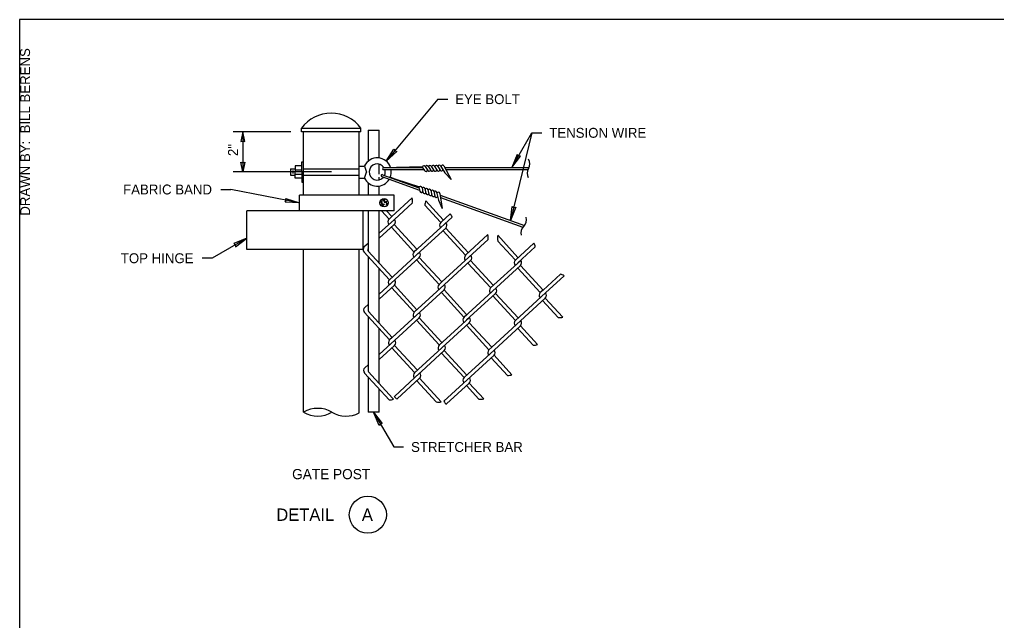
# Model space of a CAD drawing. Extents: x 99862 to 104211, y 98939 to 105076.
# Drawn here: x 99862 to 101442, y 104103 to 105076 of the extents above; entities that cross this region are included whole.
import ezdxf

# ---------------------------------------------------------------- set-up
doc = ezdxf.new("R2010")
doc.units = 0
for name, color, linetype in [('Level 1', 7, 'Continuous'), ('Level 15', 7, 'Continuous'), ('Level 2', 7, 'Continuous'), ('Level 20', 7, 'Continuous'), ('Level 4', 7, 'Continuous'), ('Level 62', 7, 'Continuous'), ('Level 7', 7, 'Continuous'), ('Level 9', 7, 'Continuous')]:
    doc.layers.add(name, color=color, linetype=linetype)

msp = doc.modelspace()

# ---------------------------------------------------------------- linework, layer by layer
at = {"layer": 'Level 1'}
msp.add_lwpolyline([(99862, 102999.5), (103151, 102999.5), (103151, 105075.5), (99862, 105075.5)], close=True, dxfattribs=at)
at = {"layer": 'Level 15'}
for p, q in [((100538.7, 104946.7), (100455.2, 104846.3)), ((100538.7, 104946.7), (100554.7, 104946.7)), ((100230.6, 104893.6), (100207.3, 104893.6)), ((100223.3, 104893.6), (100223.3, 104828.9)), ((100300.6, 104893.6), (100230.6, 104893.6)), ((100690.8, 104892.2), (100656.4, 104750.2)), ((100658.3, 104835.9), (100690.8, 104892.2)), ((100690.8, 104892.2), (100706.8, 104892.2)), ((100366.4, 104828.9), (100207.3, 104828.9)), ((100187.6, 104800.5), (100203.6, 104800.5)), ((100314.8, 104778.7), (100203.6, 104800.5)), ((100229.7, 104721.8), (100173.4, 104689.3)), ((100173.4, 104689.3), (100157.4, 104689.3)), ((100434.8, 104440.1), (100467.3, 104383.9)), ((100467.3, 104383.9), (100483.3, 104383.9))]:
    msp.add_line(p, q, dxfattribs=at)
for points in [[(100223.3, 104893.6), (100220.2, 104877.9), (100223.3, 104878.6), (100226.3, 104877.9)], [(100223.3, 104893.6), (100220.2, 104877.9), (100223.3, 104878.6), (100226.3, 104877.9)], [(100455.2, 104846.3), (100467.5, 104865.7), (100469.1, 104863), (100472.1, 104861.9)], [(100658.3, 104835.9), (100672.3, 104854.2), (100669.1, 104854.7), (100667.1, 104857.1)], [(100223.3, 104828.9), (100220.2, 104844.6), (100223.3, 104843.9), (100226.3, 104844.6)], [(100314.8, 104778.7), (100291.8, 104780.1), (100293.4, 104782.9), (100293, 104786)], [(100656.4, 104750.2), (100658.9, 104773.1), (100661.5, 104771.4), (100664.7, 104771.7)], [(100229.7, 104721.8), (100208.4, 104713), (100210.8, 104710.9), (100211.4, 104707.8)], [(100434.8, 104440.1), (100448.8, 104421.9), (100445.7, 104421.3), (100443.7, 104418.9)]]:
    msp.add_lwpolyline(points, close=True, dxfattribs=at)
at = {"layer": 'Level 2'}
for p, q in [((100300.2, 104834), (100300.2, 104823.6)), ((100300.2, 104834), (100307.8, 104834)), ((100304.2, 104831.4), (100304.2, 104826.2)), ((100307.8, 104838.9), (100307.8, 104828.8)), ((100307.9, 104832.2), (100318.4, 104832.2)), ((100321.2, 104834), (100411.5, 104834)), ((100420, 104838.5), (100423, 104828.8)), ((100450.9, 104836), (100513.4, 104835.9)), ((100450.9, 104832.7), (100515.8, 104832.7)), ((100462.1, 104836.3), (100471.9, 104836.6)), ((100471.9, 104836.6), (100514, 104837.8)), ((100514.2, 104834.8), (100517, 104831.1)), ((100518.1, 104837.9), (100522.3, 104831.1)), ((100523.1, 104838.1), (100527.4, 104831.2)), ((100528, 104838.4), (100532.4, 104831.4)), ((100532.9, 104838.6), (100537.6, 104831.3)), ((100538, 104838.7), (100542.4, 104831.7)), ((100543, 104838.8), (100550.1, 104827.5)), ((100548.4, 104838.6), (100560.3, 104816.7)), ((100549.8, 104836.1), (100686.1, 104836.1)), ((100551.7, 104832.6), (100684.4, 104832.6)), ((100300.2, 104823.6), (100307.8, 104823.6)), ((100307.8, 104818.7), (100307.8, 104828.8)), ((100307.8, 104825.3), (100318.4, 104825.3)), ((100321.1, 104823.6), (100411.6, 104823.6)), ((100420, 104819), (100423, 104828.8)), ((100448, 104821.4), (100509, 104799.5)), ((100449.1, 104824.5), (100507.8, 104803.3)), ((100461.8, 104820.3), (100469, 104818)), ((100469, 104818), (100509.1, 104804.9)), ((100550.1, 104827.5), (100560.3, 104816.7)), ((100508.2, 104802), (100509.6, 104797.6)), ((100513, 104803.6), (100514.6, 104795.8)), ((100517.7, 104802.2), (100519.4, 104794.1)), ((100522.4, 104800.7), (100524.2, 104792.7)), ((100527.1, 104799.2), (100529.1, 104790.8)), ((100531.9, 104797.6), (100533.7, 104789.6)), ((100536.7, 104796), (100539.5, 104783)), ((100541.7, 104794), (100545.5, 104769.5)), ((100542.2, 104791.2), (100678.7, 104742.2)), ((100542.8, 104787.3), (100676.2, 104739.4)), ((100539.5, 104783), (100545.5, 104769.5))]:
    msp.add_line(p, q, dxfattribs=at)
for points in [[(100318.4, 104828.8), (100318.4, 104838.9), (100307.8, 104838.9)], [(100318.4, 104838.9), (100318.4, 104845.1), (100321.1, 104845.1)], [(100318.4, 104818.7), (100318.4, 104812.4), (100321.1, 104812.4), (100321.1, 104845.1)], [(100411.6, 104838.5), (100420, 104838.5)], [(100318.4, 104828.8), (100318.4, 104818.7), (100307.8, 104818.7)], [(100411.6, 104819), (100420, 104819)]]:
    msp.add_lwpolyline(points, dxfattribs=at)
msp.add_circle((100451.6, 104779), 6.76, dxfattribs=at)
for centre, radius, start, end in [((100440.6, 104828.8), 22.8, 18.3425, 154.6231), ((100672, 104842), 15.4, 330, 30), ((100440.6, 104828.8), 13, 33.4715, 320.4532), ((100450.9, 104834.3), 1.6, 92.6316, 272.6316), ((100440.6, 104828.8), 13, 334.9419, 17.7718), ((100440.6, 104828.8), 22.8, 337.2003, 10.0184), ((100516, 104836.5), 2.5, 29.8429, 222.7267), ((100519.2, 104832.3), 2.5, 208.4651, 356.4133), ((100521, 104836.7), 2.5, 28.1747, 168.7798), ((100524.4, 104832.4), 2.5, 211.7102, 348.8374), ((100526, 104836.8), 2.5, 26.119, 168.8374), ((100529.5, 104832.6), 2.5, 209.4537, 349.9106), ((100531, 104837), 2.5, 24.8575, 168.9693), ((100534.5, 104832.7), 2.5, 212.2145, 349.0096), ((100536, 104837.1), 2.5, 25.6492, 169.089), ((100539.5, 104832.9), 2.5, 204.8575, 348.3868), ((100541, 104837.3), 2.5, 27.3875, 169.0102), ((100544.5, 104833.1), 2.5, 212.3243, 346.9886), ((100546.2, 104837.4), 2.5, 28.445, 175.2837), ((100698.6, 104826.7), 15.4, 150, 206.9934), ((100440.6, 104828.8), 22.8, 205.3769, 329.0704), ((100448.4, 104823), 1.6, 72.8951, 252.8951), ((100510.5, 104803), 2.5, 10.1064, 202.9901), ((100515.3, 104801.5), 2.5, 8.4381, 149.0432), ((100520, 104799.9), 2.5, 6.3824, 149.1008), ((100524.8, 104798.4), 2.5, 5.1209, 149.2328), ((100529.5, 104796.8), 2.5, 5.9127, 149.3525), ((100512.1, 104798), 2.5, 188.7285, 336.6768), ((100517.1, 104796.3), 2.5, 191.9736, 329.1008), ((100521.8, 104794.8), 2.5, 189.7171, 330.174), ((100526.6, 104793.2), 2.5, 192.478, 329.273), ((100531.4, 104791.7), 2.5, 185.1209, 328.6502), ((100534.3, 104795.3), 2.5, 7.6509, 149.2736), ((100536.1, 104790.2), 2.5, 192.5877, 327.252), ((100539.3, 104793.7), 2.5, 8.7084, 155.5471), ((100666.6, 104751.7), 15.4, 314.8676, 14.8676), ((100688.3, 104729.9), 15.4, 134.8676, 191.861)]:
    msp.add_arc(centre, radius, start, end, dxfattribs=at)
at = {"layer": 'Level 4'}
for p, q in [((100497.1, 104786.9), (100464.2, 104756.6)), ((100497.7, 104779.2), (100468.3, 104752.2)), ((100517.5, 104775), (100542.9, 104747.4)), ((100519.2, 104782.1), (100547.3, 104751.4)), ((100468.3, 104752.2), (100443.9, 104729.8)), ((100447.4, 104766.1), (100459.8, 104752.6)), ((100455.5, 104766.1), (100464.2, 104756.6)), ((100464.2, 104756.6), (100459.8, 104752.6)), ((100561.6, 104755.8), (100500.4, 104699.5)), ((100558.7, 104761.3), (100543.2, 104747)), ((100467.9, 104743.8), (100443.9, 104721.7)), ((100459.5, 104744.1), (100459.5, 104744.1)), ((100463.5, 104739.7), (100500, 104699.9)), ((100467.9, 104743.8), (100504.4, 104704)), ((100551.3, 104738.2), (100504.4, 104695.1)), ((100542.9, 104747.4), (100543.2, 104747)), ((100542.9, 104738.5), (100542.9, 104738.5)), ((100547.3, 104751.4), (100547.6, 104751.1)), ((100551.3, 104738.2), (100587.9, 104698.4)), ((100546.9, 104734.1), (100583.4, 104694.3)), ((100619.6, 104727.5), (100583.4, 104694.3)), ((100635.4, 104726.4), (100668.2, 104690.7)), ((100425.7, 104713.2), (100419.7, 104707.6)), ((100620, 104719.8), (100545, 104650.9)), ((100635.9, 104717.1), (100663.8, 104686.7)), ((100694.1, 104713.8), (100664.1, 104686.3)), ((100696.3, 104707.7), (100668.2, 104681.9)), ((100419.3, 104699.1), (100459.9, 104654.9)), ((100425.8, 104701), (100464.3, 104659)), ((100508.5, 104690.7), (100443.9, 104631.4)), ((100508.8, 104699.2), (100460.2, 104654.5)), ((100500, 104699.9), (100500.4, 104699.5)), ((100500, 104691.1), (100500, 104691.1)), ((100504.8, 104703.6), (100500.4, 104699.5)), ((100504.4, 104704), (100504.8, 104703.6)), ((100508.5, 104690.7), (100545, 104650.9)), ((100668.5, 104690.3), (100664.1, 104686.3)), ((100668.2, 104690.7), (100668.5, 104690.3)), ((100504.1, 104686.6), (100540.6, 104646.9)), ((100591.5, 104685.5), (100549.1, 104646.5)), ((100672.2, 104677.4), (100581.1, 104593.8)), ((100583.1, 104685.9), (100583.1, 104685.9)), ((100587.1, 104681.4), (100623.6, 104641.7)), ((100591.5, 104685.5), (100628.1, 104645.7)), ((100672.6, 104685.9), (100624, 104641.3)), ((100663.8, 104686.7), (100664.1, 104686.3)), ((100663.8, 104677.8), (100663.8, 104677.8)), ((100667.8, 104673.4), (100704.3, 104633.6)), ((100672.2, 104677.4), (100708.8, 104637.7)), ((100464.3, 104659), (100464.6, 104658.6)), ((100737, 104663.6), (100708.8, 104637.7)), ((100742.8, 104660.8), (100712.8, 104633.2)), ((100468.3, 104645.7), (100443.9, 104623.3)), ((100459.9, 104654.9), (100460.2, 104654.5)), ((100459.9, 104646.1), (100459.9, 104646.1)), ((100463.9, 104641.7), (100500.4, 104601.9)), ((100468.3, 104645.7), (100504.9, 104605.9)), ((100549.1, 104646.5), (100500.4, 104601.9)), ((100545, 104650.9), (100540.6, 104646.9)), ((100623.6, 104641.7), (100624, 104641.3)), ((100628.1, 104645.7), (100628.4, 104645.4)), ((100548.7, 104638), (100464.9, 104561.2)), ((100540.2, 104638.4), (100540.2, 104638.4)), ((100544.3, 104634), (100580.8, 104594.2)), ((100548.7, 104638), (100585.2, 104598.2)), ((100632.1, 104632.5), (100585.2, 104589.4)), ((100623.6, 104632.8), (100623.6, 104632.8)), ((100627.7, 104628.4), (100664.2, 104588.6)), ((100632.1, 104632.5), (100668.6, 104592.7)), ((100712.8, 104633.2), (100664.2, 104588.6)), ((100708.8, 104637.7), (100704.3, 104633.6)), ((100425.7, 104614.7), (100420.3, 104609.8)), ((100712.4, 104624.8), (100625.8, 104545.2)), ((100704, 104625.1), (100704, 104625.1)), ((100708, 104620.7), (100733.2, 104593.3)), ((100712.4, 104624.8), (100740.8, 104593.8)), ((100420, 104601.3), (100460.5, 104557.1)), ((100426.4, 104603.1), (100464.9, 104561.2)), ((100580.8, 104594.2), (100581.1, 104593.8)), ((100585.5, 104597.9), (100581.1, 104593.8)), ((100585.2, 104598.2), (100585.5, 104597.9)), ((100508.5, 104593), (100469, 104556.7)), ((100500.1, 104593.4), (100500.1, 104593.4)), ((100589.2, 104585), (100501.1, 104504)), ((100504.1, 104589), (100540.6, 104549.2)), ((100508.5, 104593), (100545.1, 104553.2)), ((100589.6, 104593.5), (100541, 104548.8)), ((100580.8, 104585.3), (100580.8, 104585.3)), ((100584.8, 104580.9), (100621.3, 104541.1)), ((100589.2, 104585), (100625.8, 104545.2)), ((100672.3, 104579.8), (100629.8, 104540.8)), ((100663.8, 104580.1), (100663.8, 104580.1)), ((100672.3, 104579.8), (100700, 104549.6)), ((100667.9, 104575.7), (100692.9, 104548.4)), ((100469, 104556.7), (100443.9, 104533.7)), ((100468.6, 104548.3), (100443.9, 104525.6)), ((100460.2, 104548.6), (100460.2, 104548.6)), ((100464.9, 104561.2), (100460.5, 104557.1)), ((100468.6, 104548.3), (100505.2, 104508.5)), ((100540.6, 104549.2), (100541, 104548.8)), ((100545.1, 104553.2), (100545.4, 104552.9)), ((100464.2, 104544.2), (100500.7, 104504.4)), ((100549.1, 104540), (100505.1, 104499.6)), ((100540.6, 104540.3), (100540.6, 104540.3)), ((100544.7, 104535.9), (100581.2, 104496.1)), ((100629.5, 104532.3), (100548.5, 104458)), ((100549.1, 104540), (100585.6, 104500.2)), ((100629.8, 104540.8), (100581.2, 104496.1)), ((100621, 104532.7), (100621, 104532.7)), ((100625.8, 104545.2), (100621.3, 104541.1)), ((100629.5, 104532.3), (100658.4, 104500.8)), ((100425.7, 104517), (100420.4, 104512.1)), ((100625, 104528.2), (100651.2, 104499.7)), ((100420, 104503.6), (100459.7, 104460.4)), ((100426.5, 104505.5), (100465.4, 104463.1)), ((100509.6, 104503.7), (100468.3, 104465.8)), ((100500.7, 104504.4), (100501.1, 104504)), ((100505.5, 104508.1), (100501.1, 104504)), ((100505.2, 104508.5), (100505.5, 104508.1)), ((100509.2, 104495.2), (100472.8, 104461.8)), ((100500.7, 104495.6), (100500.7, 104495.6)), ((100504.8, 104491.2), (100536, 104457.1)), ((100509.2, 104495.2), (100544.1, 104457.1)), ((100589.3, 104487.3), (100552.4, 104453.5)), ((100580.8, 104487.7), (100580.8, 104487.7)), ((100584.9, 104483.2), (100604.9, 104461.5)), ((100589.3, 104487.3), (100612.9, 104461.6)), ((100467, 104461.3), (100465.4, 104463.1))]:
    msp.add_line(p, q, dxfattribs=at)
for centre, radius, start, end in [((100476.6, 104781.6), 21.2, 353.5358, 14.382), ((100538.7, 104773.8), 21.2, 157.0142, 176.7322), ((100463.9, 104748.2), 6, 132.5495, 222.5495), ((100463.9, 104748.2), 6, 312.5495, 42.5495), ((100541.5, 104748.9), 21.2, 18.9361, 35.7874), ((100547.3, 104742.6), 6, 132.5495, 222.5495), ((100547.3, 104742.6), 6, 312.5495, 42.5495), ((100601.8, 104722.6), 18.5, 351.3089, 15.4972), ((100653.5, 104722.6), 18.5, 167.9956, 197.3612), ((100423.7, 104703.2), 6, 132.5495, 222.5495), ((100428, 104703), 3, 138.341, 222.5495), ((100671.4, 104702), 25.5, 12.7654, 27.4071), ((100504.4, 104695.1), 6, 132.5495, 222.5495), ((100504.4, 104695.1), 6, 312.5495, 42.5495), ((100587.5, 104689.9), 6, 132.5495, 222.5495), ((100587.5, 104689.9), 6, 312.5495, 42.5495), ((100668.2, 104681.9), 6, 132.5495, 222.5495), ((100668.2, 104681.9), 6, 312.5495, 42.5495), ((100729, 104639.4), 25.5, 57.2673, 71.8619), ((100464.3, 104650.1), 6, 132.5495, 222.5495), ((100464.3, 104650.1), 6, 312.5495, 42.5495), ((100544.6, 104642.4), 6, 132.5495, 222.5495), ((100544.6, 104642.4), 6, 312.5495, 42.5495), ((100628, 104636.9), 6, 132.5495, 222.5495), ((100628, 104636.9), 6, 312.5495, 42.5495), ((100708.4, 104629.2), 6, 132.5495, 222.5495), ((100708.4, 104629.2), 6, 312.5495, 42.5495), ((100424.4, 104605.4), 6, 132.5495, 222.5495), ((100428.6, 104605.2), 3, 164.0506, 222.5495), ((100504.5, 104597.5), 6, 132.5495, 222.5495), ((100504.5, 104597.5), 6, 312.5495, 42.5495), ((100585.2, 104589.4), 6, 132.5495, 222.5495), ((100735.7, 104611.8), 18.6, 262.1267, 285.8803), ((100585.2, 104589.4), 6, 312.5495, 42.5495), ((100668.2, 104584.2), 6, 132.5495, 222.5495), ((100668.2, 104584.2), 6, 312.5495, 42.5495), ((100464.6, 104552.7), 6, 132.5495, 222.5495), ((100464.6, 104552.7), 6, 312.5495, 42.5495), ((100545, 104544.4), 6, 132.5495, 222.5495), ((100545, 104544.4), 6, 312.5495, 42.5495), ((100693.6, 104567.1), 18.6, 267.8743, 290.1441), ((100625.4, 104536.7), 6, 132.5495, 222.5495), ((100625.4, 104536.7), 6, 312.5495, 42.5495), ((100424.4, 104507.7), 6, 132.5495, 222.5495), ((100428.7, 104507.5), 3, 169.6409, 222.5495), ((100505.1, 104499.6), 6, 132.5495, 222.5495), ((100505.1, 104499.6), 6, 312.5495, 42.5495), ((100651, 104524.9), 25.2, 270.5383, 286.982), ((100585.3, 104491.7), 6, 132.5495, 222.5495), ((100585.3, 104491.7), 6, 312.5495, 42.5495), ((100462.1, 104471.7), 11.5, 258.0879, 295.4826), ((100477.4, 104471.7), 10.9, 212.8086, 245.0646), ((100540, 104466.2), 9.96, 246.3051, 294.3344), ((100558.4, 104462.4), 10.8, 204.2161, 236.5942), ((100608.4, 104486.5), 25.2, 262.0811, 280.3024)]:
    msp.add_arc(centre, radius, start, end, dxfattribs=at)
at = {"layer": 'Level 7'}
for p, q in [((100318.2, 104899.8), (100414, 104899.8)), ((100318.2, 104893.6), (100318.2, 104899.8)), ((100414, 104893.6), (100414, 104899.8)), ((100425.7, 104896.7), (100443.9, 104896.7)), ((100443.9, 104851.3), (100443.9, 104896.7)), ((100414, 104893.6), (100318.2, 104893.6)), ((100321.2, 104791.2), (100321.2, 104893.6)), ((100411.5, 104791.2), (100411.5, 104893.6)), ((100443.9, 104825.5), (100443.9, 104841.4)), ((100443.9, 104816.2), (100443.9, 104820.4)), ((100443.9, 104791.2), (100443.9, 104806.2)), ((100314.8, 104766.1), (100314.8, 104791.2)), ((100467.9, 104791.2), (100314.8, 104791.2)), ((100449.7, 104781.4), (100451.9, 104784.7)), ((100451.3, 104781), (100453.5, 104784.4)), ((100467.9, 104766.1), (100467.9, 104791.2)), ((100446.2, 104779), (100448.4, 104782.4)), ((100446.8, 104776.5), (100449, 104779.9)), ((100448.2, 104774.4), (100450.3, 104777.8)), ((100449.9, 104773.8), (100452.1, 104777.2)), ((100452.1, 104778.9), (100454.2, 104782.3)), ((100454.4, 104778.2), (100456.6, 104781.6)), ((100454.9, 104775.4), (100457.1, 104778.8)), ((100229.7, 104703.4), (100229.7, 104766.1)), ((100417.7, 104766.1), (100229.7, 104766.1)), ((100426.5, 104766.1), (100330, 104766.1)), ((100417.7, 104703.4), (100417.7, 104766.1)), ((100461.6, 104766.1), (100424.7, 104766.1)), ((100443.9, 104681.2), (100443.9, 104766.1)), ((100467.9, 104766.1), (100461.6, 104766.1)), ((100417.7, 104703.4), (100229.7, 104703.4)), ((100321.2, 104440.1), (100321.2, 104703.4)), ((100411.5, 104439.1), (100411.5, 104703.4)), ((100443.9, 104584.1), (100443.9, 104672.3)), ((100443.9, 104486.5), (100443.9, 104575.2)), ((100443.9, 104440.1), (100443.9, 104477.6)), ((100443.9, 104440.1), (100425.7, 104440.1))]:
    msp.add_line(p, q, dxfattribs=at)
for points in [[(100425.7, 104896.7), (100425.7, 104896.7), (100425.7, 104846)], [(100425.7, 104811.5), (100425.7, 104791.2)], [(100425.7, 104766.1), (100425.7, 104701)], [(100425.7, 104692.1), (100425.7, 104604.3)], [(100425.7, 104595), (100425.7, 104507)], [(100425.7, 104497.4), (100425.7, 104440.1)]]:
    msp.add_lwpolyline(points, dxfattribs=at)
for centre, start, end in [((100344.3, 104400.3), 60, 120), ((100344.3, 104480), 240, 300), ((100390.3, 104480), 240, 297.3184)]:
    msp.add_arc(centre, 46.1, start, end, dxfattribs=at)
msp.add_ellipse((100366.1, 104868.1), major_axis=(-58.2, 0), ratio=0.962109, start_param=3.744228, end_param=5.68055, dxfattribs=at)
at = {"layer": 'Level 9'}
msp.add_circle((100425.4, 104274.3), 30, dxfattribs=at)

# ---------------------------------------------------------------- texts
at = {"layer": 'Level 20'}
for s, height, p in [('EYE BOLT', 16, (100566.7, 104938.7)), ('TENSION WIRE', 16, (100718.8, 104884.2)), ('FABRIC BAND', 16, (100029.5, 104792.5)), ('STRETCHER BAR', 16, (100495.3, 104375.9)), ('GATE POST', 16.5, (100302.9, 104331.8)), ('DETAIL', 20, (100277.3, 104264.4)), ('A', 20, (100415.7, 104264.4))]:
    msp.add_text(s, height=height, dxfattribs=at).set_placement(p)
for s, rotation, p in [('2"', 90, (100215.3, 104854.6)), ('TOP HINGE', 360, (100025.8, 104681.3))]:
    msp.add_text(s, height=16, rotation=rotation, dxfattribs=at).set_placement(p)
at = {"layer": 'Level 62'}
msp.add_text('DRAWN BY:  BILL BERENS', height=16, rotation=90, dxfattribs=at).set_placement((99879, 104758.1))

doc.saveas('drawing.dxf')
